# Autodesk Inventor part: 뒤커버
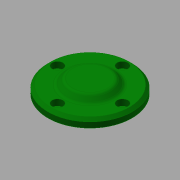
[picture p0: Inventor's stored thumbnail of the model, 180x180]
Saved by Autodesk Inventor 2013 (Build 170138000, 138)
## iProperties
Created: 2015-09
Part Number: 뒤커버
Material: 알루미늄 6061
Document SubType Name: Modeling
Designer: mduedu
Density: 1 g/cm^3
Author: mduedu
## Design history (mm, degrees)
sketch "스케치1"
  geometry: L1 (0, 7.5)-(0, -7.5); L2 (0, 7.5)-(14, 7.5); L3 (14, 7.5)-(18, 3.5); L4 (18, 3.5)-(31, 3.5); L5 (31, 3.5)-(31, -2.5); L6 (31, -2.5)-(17.5, -2.5); L7 (17.5, -2.5)-(17.5, -7.5); L8 (17.5, -7.5)-(0, -7.5); 2 further points
  constraints: 16 end point, 3 parallel, 2 perpendicular, 1 coincident, 1 horizontal, 1 midpoint, 1 vertical
  dimensions: "d0" = 15 distance of L1.start L1.end; "d1" = 4 distance between parallel lines of L4 L2; "d2" = 6 distance of L4.end L5.end; "d3" = 36 diameter of L3.end L1; "d4" = 35 diameter of L7 L1; "d5" = 62 diameter of L5 L1; "d7" = 45 deg angle of L3 L5
revolve "회전1" sketch "스케치1" stored, may be unused: angle "d8" = 90 deg
hole "구멍1" diameter "d11" = 24; stored, may be unused: countersink angle "d15" = 90 deg, drill point angle "d17" = 0 deg; dims "d9" = 10, "d10" = 10, "d12" = 6, "d13" = 4, "d14" = 2, "d16" = 8
fillet "모깎기1" dims "d18" = 3
chamfer "모따기2" distance "d22" = 2; stored, may be unused: second distance "d23" = 2, angle "d24" = 45 deg
fillet "모깎기2" dims "d25" = 3
fillet "모깎기3" dims "d26" = 3
sketch "스케치2" dims "d27" = 48
  geometry: 6 further points
  constraints: 2 vertical alignment, 1 coincident, 7 other
  dimensions: "d33" = 360 deg dimension on point (0, 0) point (0, 24) (derived)
sketch "스케치3"
  geometry: 4 further points
hole "구멍2" sketch "스케치3" at (-24, 0), (0, -24), (24, 0), (0, 24) diameter "d35" = 4.5; stored, may be unused: countersink angle "d39" = 90 deg, drill point angle "d41" = 0 deg; dims "d36" = 6, "d37" = 8, "d38" = 4.6, "d40" = 8
chamfer "모따기3" distance "d42" = 1; stored, may be unused: second distance "d43" = 2, angle "d44" = 45 deg
node "솔리드1"
